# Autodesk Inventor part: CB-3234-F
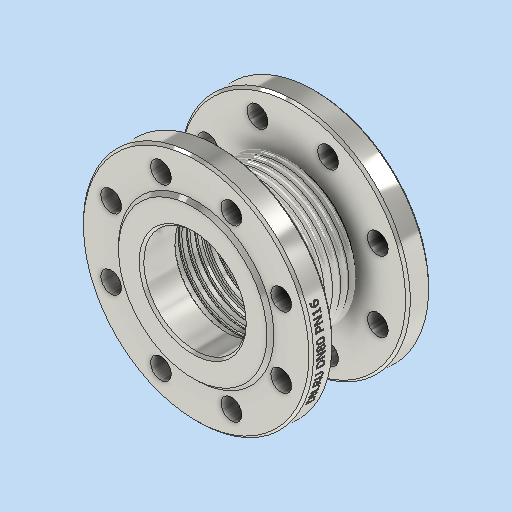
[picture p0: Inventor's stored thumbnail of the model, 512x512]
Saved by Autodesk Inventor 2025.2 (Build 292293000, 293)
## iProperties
Company: DN.RU
Created: 2026-04
Part Number: CB-3234-F
Material: Типовые
Document SubType Name: Modeling
Designer: DN.RU
Density: 6.29665 g/cm^3
Appearance: По умолчанию
Description: D140-02115
Mass: 7000 g
Surface Area: 3037.37 cm^2
Volume: 1111.7 cm^3
Author: DN.RU
Title: Компенсатор сильфонный осевой DN.ru Ду80 Ру16
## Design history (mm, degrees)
sketch "Эскиз1"
  geometry: L1 (0, 0)-(0, -55); L2 (50.5, -55)-(50.5, 0); L3 (50.5, 0)-(0, 0); L4 (50.5, 0)-(50.5, -3.5); L5 (42.5, -3.5)-(58.5, -3.5); L6 (42.5, -6)-(58.5, -6); L7 (58.5, -1)-(42.5, -1); L8 (58.5, -4)-(42.5, -4); L9 (42.5, -3)-(58.5, -3); L10 (58.5, -8)-(42.5, -8); L11 (42.5, -10)-(58.5, -10); L12 (42.5, -10.5)-(58.5, -10.5); L13 (42.5, -13)-(58.5, -13); L14 (58.5, -11)-(42.5, -11); L15 (58.5, -15)-(42.5, -15); L16 (42.5, -17)-(58.5, -17); L17 (42.5, -17.5)-(58.5, -17.5); L18 (42.5, -20)-(58.5, -20); L19 (58.5, -18)-(42.5, -18); L20 (58.5, -22)-(42.5, -22); L21 (42.5, -24)-(58.5, -24); L22 (42.5, -24.5)-(58.5, -24.5); L23 (42.5, -27)-(58.5, -27); L24 (58.5, -25)-(42.5, -25); L25 (0, -55)-(50.5, -55); L26 (50.5, -55)-(44.5, -55); L27 (50.5, -22)-(48.5, -22); L28 (44.5, -55)-(44.5, -25); L29 (50.5, -24)-(48.5, -24); L30 (48.5, -24)-(48.5, -18); L31 (50.5, -17)-(48.5, -17); L32 (48.5, -17)-(48.5, -11); L33 (50.5, -10)-(48.5, -10); L34 (48.5, -10)-(48.5, -4); L35 (50.5, -3)-(49.5, -3); L36 (49.5, -3)-(48.5, 0); L37 (0, -55)-(0, -32); L38 (0, -32)-(100, -32); L39 (100, -32)-(100, -55); L40 (100, -55)-(0, -55); L41 (50.5, -32)-(50.5, -42); L42 (50.5, -42)-(53.5, -42); L43 (53.5, -42)-(53.5, -32); L44 (53.5, -32)-(50.5, -32); A1 r 2.5 centre (42.5, -3.5) between (42.5, -1) and (42.5, -6); A2 r 2.5 centre (58.5, -3.5) between (58.5, -6) and (58.5, -1); A3 r 0.5 centre (42.5, -3.5) between (42.5, -3) and (42.5, -4); A4 r 0.5 centre (58.5, -3.5) between (58.5, -4) and (58.5, -3); A5 r 0.5 centre (42.5, -10.5) between (42.5, -10) and (42.5, -11); A6 r 2.5 centre (42.5, -10.5) between (42.5, -8) and (42.5, -13); A7 r 0.5 centre (58.5, -10.5) between (58.5, -11) and (58.5, -10); A8 r 2.5 centre (58.5, -10.5) between (58.5, -13) and (58.5, -8); A9 r 0.5 centre (42.5, -17.5) between (42.5, -17) and (42.5, -18); A10 r 2.5 centre (42.5, -17.5) between (42.5, -15) and (42.5, -20); A11 r 0.5 centre (58.5, -17.5) between (58.5, -18) and (58.5, -17); A12 r 2.5 centre (58.5, -17.5) between (58.5, -20) and (58.5, -15); A13 r 0.5 centre (42.5, -24.5) between (42.5, -24) and (42.5, -25); A14 r 2.5 centre (42.5, -24.5) between (42.5, -22) and (42.5, -27); A15 r 0.5 centre (58.5, -24.5) between (58.5, -25) and (58.5, -24); A16 r 2.5 centre (58.5, -24.5) between (58.5, -27) and (58.5, -22); 20 further points
  constraints: 96 end point, 32 point on circle, 19 point on line, 16 centre point, 7 parallel, 7 perpendicular, 6 midpoint, 4 tangent, 2 vertical, 1 horizontal, 69 other
  dimensions: "d0" = 55 distance of L1.start L1.end; "d3" = 3.5 distance of L2.end L4.end; "d4" = 8 distance of L4.end L5.end; "d5" = 5 diameter of A2; "d6" = 2 distance between parallel lines of L6 L8; "d9" = 7 distance of L4.end point (50.5, -10.5); "d15" = 2 distance of L27.start L27.end; "d16" = 2 distance of L29.start L29.end; "d17" = 2 distance of L31.start L31.end; "d18" = 2 distance of L33.start L33.end; "d19" = 1 distance of L35.start L35.end; "d27" = 44.5 distance between parallel lines of L1 L28; "d28" = 6 distance between parallel lines of L2 L28; "d29" = 23 distance of L1.end L37.end; "d30" = 100 distance of L37.end L38.end; "d31" = 10 distance of L41.start L41.end; "d32" = 3 distance of L42.end L41.end
revolve "Вращение1" sketch "Эскиз1" stored, may be unused: angle "d20" = 360 deg
sketch "Эскиз3" dims "d33" = 160
  geometry: L1 (0, 0)-(71.096, 29.449); L2 (0, 0)-(76.954, 0); C1 r 9 at (73.91, 30.615); C2 r 9 at (30.615, 73.91); C3 r 9 at (-30.615, 73.91); C4 r 9 at (-73.91, 30.615); C5 r 44.5 at (0, 0) reference; C6 r 67.5 at (0, 0); C7 r 100 at (0, 0) reference; C8 r 9 at (-73.91, -30.615); C9 r 9 at (-30.615, -73.91); C10 r 9 at (30.615, -73.91); C11 r 9 at (73.91, -30.615); 1 further point
  constraints: 9 centre point, 4 end point, 2 coincident, 1 equal length, 1 horizontal, 1 point on line, 20 other
  dimensions: "d34" = 22.5 deg angle of L2 L1; "d35" = 18 diameter of C1; "d38" = 360 deg dimension on point (0, 0) C1.centre (derived); "d40" = 135 diameter of C6
  node "Эскиз — круговой массив1" dims "d38" = 360 deg (derived)
extrude "Выдавливание1" cut sketch "Эскиз3" stored distance "d41" = 10; taper "d42" = 0 deg
extrude "Выдавливание2" cut sketch "Эскиз3" distance "d43" = 3; taper "d44" = 0 deg
chamfer "Фаска2" distance "d45" = 3; stored, may be unused: second distance "d46" = 2, angle "d47" = 45 deg
chamfer "Фаска3" distance "d48" = 2; stored, may be unused: second distance "d49" = 2, angle "d50" = 45 deg
mirror "Зеркальное отражение2"
fillet "Сопряжение2" dims "d51" = 1
node "РабПлоскость2"
sketch "Эскиз4"
  geometry: L1 (-44.383, 3.589)-(46.395, 3.589); L2 (46.395, 3.589)-(46.395, 0.413); L3 (46.395, 0.413)-(-44.383, 0.413); L4 (-44.383, 0.413)-(-44.383, 3.589); 1 further point
  constraints: 2 other
feature "Рельеф2" sketch "Эскиз4" dims "d52" = 0.1, "d53" = 0
node "Твердое тело1"
node "Эскиз — прямоугольный массив1" dims "d9" = 7, "d12" = 10
